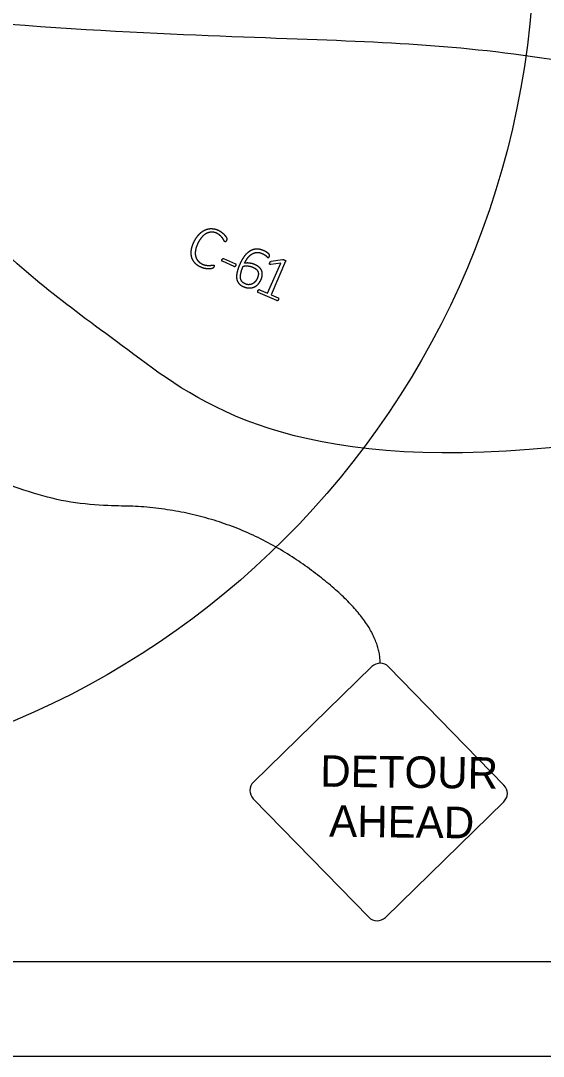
# Model space of a CAD drawing. Extents: x -202 to 1556, y 0 to 676.
# Drawn here: x 228.3 to 283.6, y 0 to 109.6 of the extents above; entities that cross this region are included whole.
import ezdxf

# ---------------------------------------------------------------- set-up
doc = ezdxf.new("R2010")
doc.units = 0
for name, color, linetype in [('Default', 7, 'Continuous'), ('GM_X_Minor_Lake', 7, 'Continuous'), ('SH_Border', 7, 'Continuous'), ('SH_Cut_Line', 7, 'Continuous'), ('SH_Data', 7, 'Continuous')]:
    doc.layers.add(name, color=color, linetype=linetype)

msp = doc.modelspace()

# ---------------------------------------------------------------- linework, layer by layer
at = {"layer": 'Default'}
for p, q in [((249.8, 84.42), (251.06, 83.86)), ((248.76, 83.52), (248.76, 83.52)), ((250.92, 83.56), (249.67, 84.12)), ((251.08, 83.67), (251.08, 83.67)), ((254.85, 84.12), (256.04, 84.31)), ((253.35, 82.3), (253.35, 82.3)), ((253.76, 82.16), (253.76, 82.16)), ((255.44, 79.96), (253.47, 80.82)), ((255.61, 80.06), (255.61, 80.06))]:
    msp.add_line(p, q, dxfattribs=at)
for points in [[(253.6, 81.12), (254.46, 80.75), (255.85, 83.94), (254.81, 83.8)], [(256.37, 84.12), (254.83, 80.59), (255.57, 80.27)]]:
    msp.add_lwpolyline(points, dxfattribs=at)
for points in [[(246.67, 86.19), (246.9, 86.65), (247.2, 86.97)], [(247.5, 86.68), (247.27, 86.42), (247.07, 86.02)], [(247.2, 86.97), (247.49, 87.28), (247.83, 87.43)], [(248.01, 87.08), (247.74, 86.95), (247.5, 86.68)], [(247.83, 87.43), (248.17, 87.59), (248.54, 87.58)], [(248.54, 87.21), (248.27, 87.21), (248.01, 87.08)], [(248.54, 87.58), (248.9, 87.57), (249.27, 87.4)], [(249.09, 87.08), (248.82, 87.21), (248.54, 87.21)], [(249.48, 86.81), (249.33, 86.96), (249.09, 87.08)], [(249.27, 87.4), (249.44, 87.31), (249.58, 87.2)], [(249.72, 86.53), (249.63, 86.67), (249.48, 86.81)], [(249.58, 87.2), (249.73, 87.09), (249.84, 86.98)], [(249.84, 86.98), (249.95, 86.86), (250.03, 86.75)], [(250.03, 86.75), (250.1, 86.63), (250.12, 86.57)], [(250.12, 86.57), (250.14, 86.51), (250.14, 86.49)], [(246.39, 85.32), (246.45, 85.73), (246.67, 86.19)], [(247.07, 86.02), (246.89, 85.64), (246.83, 85.31)], [(249.85, 86.3), (249.8, 86.4), (249.72, 86.53)], [(249.94, 86.19), (249.89, 86.21), (249.85, 86.3)], [(249.98, 86.18), (249.96, 86.18), (249.94, 86.19)], [(250.02, 86.2), (250, 86.19), (249.98, 86.18)], [(250.06, 86.25), (250.04, 86.22), (250.02, 86.2)], [(250.1, 86.32), (250.08, 86.28), (250.06, 86.25)], [(250.13, 86.39), (250.12, 86.36), (250.1, 86.32)], [(250.14, 86.44), (250.14, 86.41), (250.13, 86.39)], [(250.14, 86.49), (250.15, 86.46), (250.14, 86.44)], [(246.42, 84.58), (246.33, 84.92), (246.39, 85.32)], [(246.74, 83.97), (246.51, 84.23), (246.42, 84.58)], [(246.83, 85.31), (246.77, 84.97), (246.83, 84.69)], [(246.83, 84.69), (246.88, 84.42), (247.06, 84.2)], [(249.64, 84.31), (249.68, 84.39), (249.72, 84.41)], [(249.72, 84.41), (249.76, 84.44), (249.8, 84.42)], [(252.09, 84.78), (251.92, 84.57), (251.77, 84.32)], [(252.02, 83.93), (252.16, 84.23), (252.35, 84.48)], [(252.48, 85.13), (252.27, 84.98), (252.09, 84.78)], [(252.35, 84.48), (252.54, 84.73), (252.78, 84.88)], [(252.93, 85.36), (252.68, 85.28), (252.48, 85.13)], [(252.78, 84.88), (253.01, 85.03), (253.28, 85.06)], [(253.45, 85.41), (253.17, 85.43), (252.93, 85.36)], [(253.28, 85.06), (253.56, 85.09), (253.86, 84.96)], [(254.04, 85.25), (253.72, 85.39), (253.45, 85.41)], [(253.86, 84.96), (254.02, 84.89), (254.13, 84.82)], [(254.26, 85.14), (254.15, 85.2), (254.04, 85.25)], [(254.13, 84.82), (254.23, 84.75), (254.31, 84.69)], [(254.45, 85.02), (254.36, 85.08), (254.26, 85.14)], [(254.31, 84.69), (254.38, 84.62), (254.42, 84.58)], [(254.42, 84.58), (254.47, 84.53), (254.5, 84.52)], [(254.58, 84.9), (254.53, 84.95), (254.45, 85.02)], [(254.5, 84.52), (254.53, 84.51), (254.55, 84.51)], [(254.55, 84.51), (254.57, 84.51), (254.58, 84.53)], [(254.65, 84.82), (254.64, 84.84), (254.58, 84.9)], [(254.58, 84.53), (254.6, 84.54), (254.61, 84.57)], [(254.61, 84.57), (254.62, 84.6), (254.64, 84.63)], [(254.64, 84.63), (254.65, 84.66), (254.66, 84.68)], [(254.67, 84.77), (254.66, 84.79), (254.65, 84.82)], [(254.66, 84.68), (254.66, 84.71), (254.67, 84.73)], [(254.67, 84.73), (254.67, 84.75), (254.67, 84.77)], [(247.33, 83.53), (246.97, 83.7), (246.74, 83.97)], [(247.06, 84.2), (247.24, 83.98), (247.53, 83.84)], [(247.76, 83.37), (247.55, 83.42), (247.33, 83.53)], [(247.53, 83.84), (247.77, 83.72), (247.98, 83.7)], [(248.14, 83.32), (247.97, 83.33), (247.76, 83.37)], [(247.98, 83.7), (248.19, 83.67), (248.35, 83.68)], [(248.44, 83.33), (248.31, 83.31), (248.14, 83.32)], [(248.35, 83.68), (248.51, 83.7), (248.62, 83.72)], [(248.6, 83.36), (248.56, 83.35), (248.44, 83.33)], [(248.66, 83.39), (248.65, 83.38), (248.6, 83.36)], [(248.62, 83.72), (248.73, 83.74), (248.78, 83.72)], [(248.7, 83.42), (248.68, 83.4), (248.66, 83.39)], [(248.73, 83.46), (248.72, 83.44), (248.7, 83.42)], [(248.76, 83.52), (248.75, 83.49), (248.73, 83.46)], [(248.8, 83.6), (248.79, 83.57), (248.76, 83.52)], [(248.78, 83.72), (248.8, 83.71), (248.8, 83.69)], [(248.8, 83.69), (248.81, 83.68), (248.81, 83.66)], [(248.81, 83.66), (248.81, 83.64), (248.8, 83.6)], [(249.62, 84.18), (249.61, 84.22), (249.64, 84.31)], [(249.67, 84.12), (249.63, 84.14), (249.62, 84.18)], [(251, 83.56), (250.96, 83.54), (250.92, 83.56)], [(251.08, 83.67), (251.04, 83.59), (251, 83.56)], [(251.06, 83.86), (251.07, 83.85), (251.09, 83.84)], [(251.1, 83.75), (251.1, 83.71), (251.08, 83.67)], [(251.09, 83.84), (251.1, 83.82), (251.1, 83.8)], [(251.1, 83.8), (251.11, 83.78), (251.1, 83.75)], [(251.52, 83.82), (251.39, 83.53), (251.31, 83.27)], [(251.77, 84.32), (251.63, 84.08), (251.52, 83.82)], [(251.63, 82.87), (251.7, 83.18), (251.88, 83.61)], [(251.88, 83.61), (251.99, 83.63), (252.12, 83.63)], [(252.25, 83.94), (252.12, 83.94), (252.02, 83.93)], [(252.12, 83.63), (252.25, 83.64), (252.39, 83.63)], [(252.51, 83.93), (252.37, 83.95), (252.25, 83.94)], [(252.39, 83.63), (252.52, 83.62), (252.66, 83.58)], [(252.8, 83.88), (252.65, 83.91), (252.51, 83.93)], [(252.66, 83.58), (252.8, 83.55), (252.92, 83.49)], [(253.1, 83.77), (252.95, 83.84), (252.8, 83.88)], [(252.92, 83.49), (253.15, 83.39), (253.28, 83.26)], [(253.61, 83.45), (253.43, 83.63), (253.1, 83.77)], [(253.86, 83.06), (253.79, 83.27), (253.61, 83.45)], [(254.67, 83.89), (254.68, 83.92), (254.7, 83.97)], [(254.67, 83.83), (254.66, 83.85), (254.67, 83.89)], [(254.72, 83.8), (254.69, 83.8), (254.67, 83.83)], [(254.7, 83.97), (254.72, 84.01), (254.73, 84.04)], [(254.81, 83.8), (254.75, 83.79), (254.72, 83.8)], [(254.73, 84.04), (254.75, 84.07), (254.77, 84.08)], [(254.77, 84.08), (254.79, 84.1), (254.81, 84.11)], [(254.81, 84.11), (254.83, 84.12), (254.85, 84.12)], [(256.04, 84.31), (256.06, 84.32), (256.07, 84.32)], [(256.07, 84.32), (256.09, 84.32), (256.11, 84.31)], [(256.11, 84.31), (256.14, 84.31), (256.16, 84.3)], [(256.16, 84.3), (256.19, 84.29), (256.22, 84.27)], [(256.22, 84.27), (256.27, 84.25), (256.31, 84.23)], [(256.31, 84.23), (256.34, 84.21), (256.36, 84.19)], [(256.36, 84.19), (256.37, 84.17), (256.38, 84.15)], [(256.38, 84.15), (256.38, 84.13), (256.37, 84.12)], [(251.19, 82.78), (251.16, 82.55), (251.18, 82.35)], [(251.18, 82.35), (251.2, 82.15), (251.28, 81.98)], [(251.31, 83.27), (251.23, 83.01), (251.19, 82.78)], [(251.59, 82.34), (251.56, 82.56), (251.63, 82.87)], [(251.75, 81.97), (251.62, 82.12), (251.59, 82.34)], [(253.35, 82.3), (253.28, 82.13), (253.16, 81.99)], [(253.28, 83.26), (253.41, 83.14), (253.45, 82.98)], [(253.47, 82.66), (253.44, 82.48), (253.35, 82.3)], [(253.45, 82.98), (253.5, 82.83), (253.47, 82.66)], [(253.76, 82.16), (253.86, 82.39), (253.89, 82.62)], [(253.89, 82.62), (253.92, 82.85), (253.86, 83.06)], [(251.28, 81.98), (251.37, 81.81), (251.52, 81.67)], [(251.52, 81.67), (251.67, 81.54), (251.9, 81.44)], [(252.09, 81.73), (251.87, 81.82), (251.75, 81.97)], [(251.9, 81.44), (252.25, 81.29), (252.54, 81.3)], [(252.51, 81.65), (252.31, 81.63), (252.09, 81.73)], [(252.87, 81.75), (252.71, 81.66), (252.51, 81.65)], [(252.54, 81.3), (252.83, 81.3), (253.07, 81.42)], [(253.16, 81.99), (253.04, 81.84), (252.87, 81.75)], [(253.07, 81.42), (253.31, 81.53), (253.48, 81.73)], [(253.47, 81.07), (253.49, 81.1), (253.51, 81.11)], [(253.48, 81.73), (253.65, 81.93), (253.76, 82.16)], [(253.51, 81.11), (253.54, 81.13), (253.56, 81.13)], [(253.56, 81.13), (253.58, 81.13), (253.6, 81.12)], [(253.41, 80.94), (253.42, 80.97), (253.43, 81.01)], [(253.42, 80.88), (253.41, 80.9), (253.41, 80.94)], [(253.44, 80.84), (253.42, 80.85), (253.42, 80.88)], [(253.43, 81.01), (253.45, 81.05), (253.47, 81.07)], [(253.47, 80.82), (253.45, 80.82), (253.44, 80.84)], [(255.57, 80), (255.54, 79.97), (255.52, 79.96)], [(255.57, 80.27), (255.59, 80.26), (255.61, 80.24)], [(255.61, 80.06), (255.59, 80.02), (255.57, 80)], [(255.61, 80.24), (255.62, 80.22), (255.63, 80.19)], [(255.63, 80.13), (255.62, 80.1), (255.61, 80.06)], [(255.63, 80.19), (255.63, 80.17), (255.63, 80.13)], [(255.48, 79.95), (255.46, 79.95), (255.44, 79.96)], [(255.52, 79.96), (255.5, 79.95), (255.48, 79.95)]]:
    msp.add_open_spline(points, degree=2, dxfattribs=at)
at = {"layer": 'GM_X_Minor_Lake'}
for points in [[(252.97, 29.02), (265.49, 41.24)], [(267.26, 41.21), (279.48, 28.69)], [(265.17, 14.72), (252.94, 27.25)], [(279.46, 26.92), (266.93, 14.7)]]:
    msp.add_lwpolyline(points, dxfattribs=at)
for centre, start, end in [((266.37, 40.34), 44.2934, 134.2934), ((253.84, 28.12), 134.2934, 224.2934), ((278.59, 27.82), 314.2934, 44.2934), ((266.06, 15.59), 224.2934, 314.2934)]:
    msp.add_arc(centre, 1.25, start, end, dxfattribs=at)
at = {"layer": 'SH_Border'}
msp.add_lwpolyline([(30, 430), (670, 430), (670, 10), (30, 10)], close=True, dxfattribs=at)
at = {"layer": 'SH_Cut_Line'}
msp.add_lwpolyline([(0, 0), (680, 0), (680, 440), (0, 440)], close=True, dxfattribs=at)
at = {"layer": 'SH_Data'}
msp.add_circle((192.68, 118.45), 90, dxfattribs=at)
for points, degree in [([(318.25, 98.64), (296.15, 103.63), (275.17, 107.57), (247.73, 107.51), (203.85, 110.62), (195.4, 115.77)], 3), ([(284.72, 64.43), (256.93, 61.67), (237.17, 76.82), (226.21, 84.28), (208.97, 103.33), (195.2, 105.52)], 3), ([(266.38, 41.59), (266.38, 46.46), (249.2, 58.25), (227.22, 58.25), (200.99, 77.27), (195.2, 90.79)], 2)]:
    msp.add_open_spline(points, degree=degree, dxfattribs=at)

# ---------------------------------------------------------------- texts
at = {"layer": 'GM_X_Minor_Lake'}
for s, p in [('DETOUR', (260.02, 28.53)), ('AHEAD', (260.96, 23.24))]:
    msp.add_text(s, height=3.333, rotation=359.2934, dxfattribs=at).set_placement(p)

doc.saveas('drawing.dxf')
